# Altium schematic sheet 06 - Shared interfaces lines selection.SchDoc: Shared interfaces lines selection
size A3; PageSetup: Record=PageOptions¦CenterHorizontal=True¦CenterVertical=True¦PrintScale=0.70¦XCorrection=1.00¦YCorrection=1.00¦PrintKind=0¦BorderSize=5000000¦LeftOffset=0¦BottomOffset=0¦Orientation=2¦PaperLength=4200¦PaperWidth=2970¦Scale=100¦PaperSource=7¦PrintQuality=600¦MediaType=1¦DitherType=10¦PaperKind=A4¦PrintScaleMode=1; Author: Juan Anzola; SheetNumber: 6; SheetTotal: 20
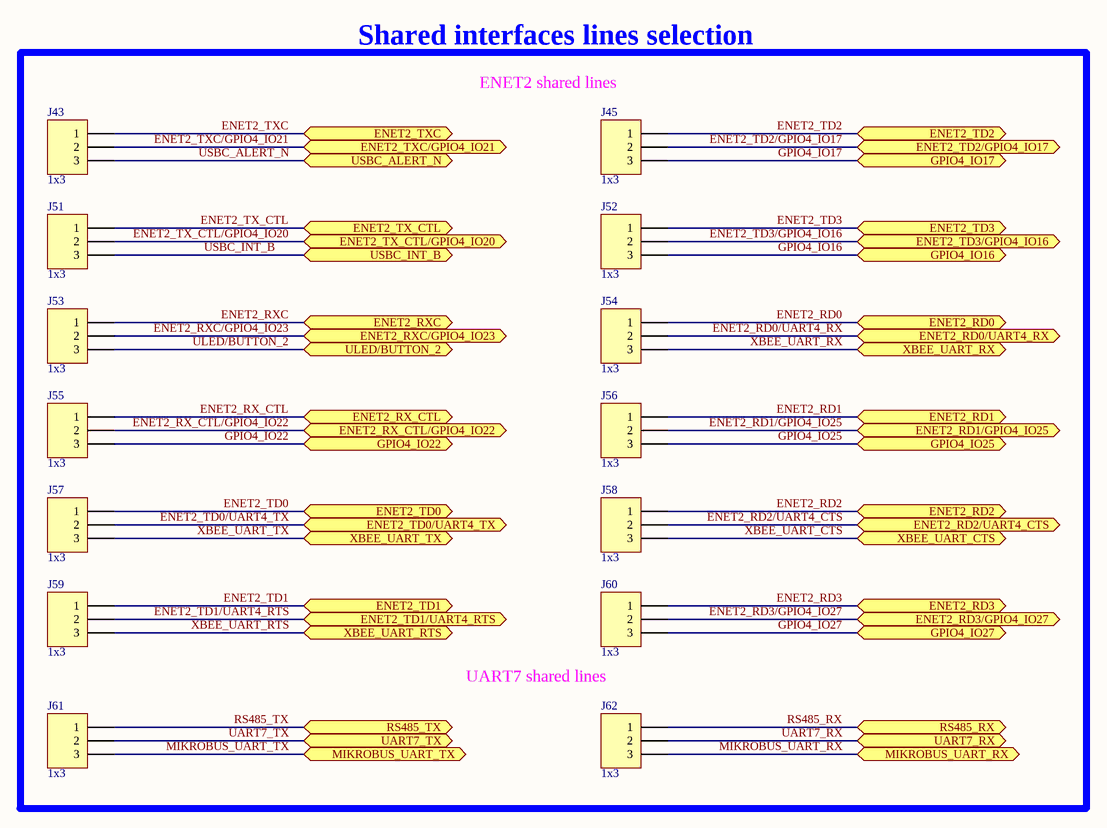
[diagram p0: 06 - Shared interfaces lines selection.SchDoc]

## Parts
J43  1x3  [SAMTEC_TSW-103-07-G-S]
J45  1x3  [SAMTEC_TSW-103-07-G-S]
J51  1x3  [SAMTEC_TSW-103-07-G-S]
J52  1x3  [SAMTEC_TSW-103-07-G-S]
J53  1x3  [SAMTEC_TSW-103-07-G-S]
J54  1x3  [SAMTEC_TSW-103-07-G-S]
J55  1x3  [SAMTEC_TSW-103-07-G-S]
J56  1x3  [SAMTEC_TSW-103-07-G-S]
J57  1x3  [SAMTEC_TSW-103-07-G-S]
J58  1x3  [SAMTEC_TSW-103-07-G-S]
J59  1x3  [SAMTEC_TSW-103-07-G-S]
J60  1x3  [SAMTEC_TSW-103-07-G-S]
J61  1x3  [SAMTEC_TSW-103-07-G-S]
J62  1x3  [SAMTEC_TSW-103-07-G-S]

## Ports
ENET2_RD0 (bidir), ENET2_RD0/UART4_RX (bidir), ENET2_RD1 (bidir), ENET2_RD1/GPIO4_IO25 (bidir), ENET2_RD2 (bidir), ENET2_RD2/UART4_CTS (bidir), ENET2_RD3 (bidir), ENET2_RD3/GPIO4_IO27 (bidir), ENET2_RX_CTL (bidir), ENET2_RX_CTL/GPIO4_IO22 (bidir), ENET2_RXC (bidir), ENET2_RXC/GPIO4_IO23 (bidir), ENET2_TD0 (bidir), ENET2_TD0/UART4_TX (bidir), ENET2_TD1 (bidir), ENET2_TD1/UART4_RTS (bidir), ENET2_TD2 (bidir), ENET2_TD2/GPIO4_IO17 (bidir), ENET2_TD3 (bidir), ENET2_TD3/GPIO4_IO16 (bidir), ENET2_TX_CTL (bidir), ENET2_TX_CTL/GPIO4_IO20 (bidir), ENET2_TXC (bidir), ENET2_TXC/GPIO4_IO21 (bidir), GPIO4_IO16 (bidir), GPIO4_IO17 (bidir), GPIO4_IO22 (bidir), GPIO4_IO25 (bidir), GPIO4_IO27 (bidir), MIKROBUS_UART_RX (bidir), MIKROBUS_UART_TX (bidir), RS485_RX (bidir), RS485_TX (bidir), UART7_RX (bidir), UART7_TX (bidir), ULED/BUTTON_2 (bidir), USBC_ALERT_N (bidir), USBC_INT_B (bidir), XBEE_UART_CTS (bidir), XBEE_UART_RTS (bidir), XBEE_UART_RX (bidir), XBEE_UART_TX (bidir)

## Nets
ENET2_RD0: J54.1 ; port ENET2_RD0
ENET2_RD0/UART4_RX: J54.2 ; port ENET2_RD0/UART4_RX
ENET2_RD1: J56.1 ; port ENET2_RD1
ENET2_RD1/GPIO4_IO25: J56.2 ; port ENET2_RD1/GPIO4_IO25
ENET2_RD2: J58.1 ; port ENET2_RD2
ENET2_RD2/UART4_CTS: J58.2 ; port ENET2_RD2/UART4_CTS
ENET2_RD3: J60.1 ; port ENET2_RD3
ENET2_RD3/GPIO4_IO27: J60.2 ; port ENET2_RD3/GPIO4_IO27
ENET2_RX_CTL: J55.1 ; port ENET2_RX_CTL
ENET2_RX_CTL/GPIO4_IO22: J55.2 ; port ENET2_RX_CTL/GPIO4_IO22
ENET2_RXC: J53.1 ; port ENET2_RXC
ENET2_RXC/GPIO4_IO23: J53.2 ; port ENET2_RXC/GPIO4_IO23
ENET2_TD0: J57.1 ; port ENET2_TD0
ENET2_TD0/UART4_TX: J57.2 ; port ENET2_TD0/UART4_TX
ENET2_TD1: J59.1 ; port ENET2_TD1
ENET2_TD1/UART4_RTS: J59.2 ; port ENET2_TD1/UART4_RTS
ENET2_TD2: J45.1 ; port ENET2_TD2
ENET2_TD2/GPIO4_IO17: J45.2 ; port ENET2_TD2/GPIO4_IO17
ENET2_TD3: J52.1 ; port ENET2_TD3
ENET2_TD3/GPIO4_IO16: J52.2 ; port ENET2_TD3/GPIO4_IO16
ENET2_TX_CTL: J51.1 ; port ENET2_TX_CTL
ENET2_TX_CTL/GPIO4_IO20: J51.2 ; port ENET2_TX_CTL/GPIO4_IO20
ENET2_TXC: J43.1 ; port ENET2_TXC
ENET2_TXC/GPIO4_IO21: J43.2 ; port ENET2_TXC/GPIO4_IO21
GPIO4_IO16: J52.3 ; port GPIO4_IO16
GPIO4_IO17: J45.3 ; port GPIO4_IO17
GPIO4_IO22: J55.3 ; port GPIO4_IO22
GPIO4_IO25: J56.3 ; port GPIO4_IO25
GPIO4_IO27: J60.3 ; port GPIO4_IO27
MIKROBUS_UART_RX: J62.3 ; port MIKROBUS_UART_RX
MIKROBUS_UART_TX: J61.3 ; port MIKROBUS_UART_TX
RS485_RX: J62.1 ; port RS485_RX
RS485_TX: J61.1 ; port RS485_TX
UART7_RX: J62.2 ; port UART7_RX
UART7_TX: J61.2 ; port UART7_TX
ULED/BUTTON_2: J53.3 ; port ULED/BUTTON_2
USBC_ALERT_N: J43.3 ; port USBC_ALERT_N
USBC_INT_B: J51.3 ; port USBC_INT_B
XBEE_UART_CTS: J58.3 ; port XBEE_UART_CTS
XBEE_UART_RTS: J59.3 ; port XBEE_UART_RTS
XBEE_UART_RX: J54.3 ; port XBEE_UART_RX
XBEE_UART_TX: J57.3 ; port XBEE_UART_TX

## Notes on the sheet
- Shared interfaces lines selection
- (near J45) ENET2 shared lines
- UART7 shared lines

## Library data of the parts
J43 J45 J51-J62 = 1002832: CONN HEADER 3POS .100" SGL GOLD; Part_Type: Connector; Manufacturer: Samtec; Manufacturer_Part_Number: TSW-103-07-G-S; Digi_PN: 00120003; Component_Life_Cycle_State: Pending; Area: 19,3548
